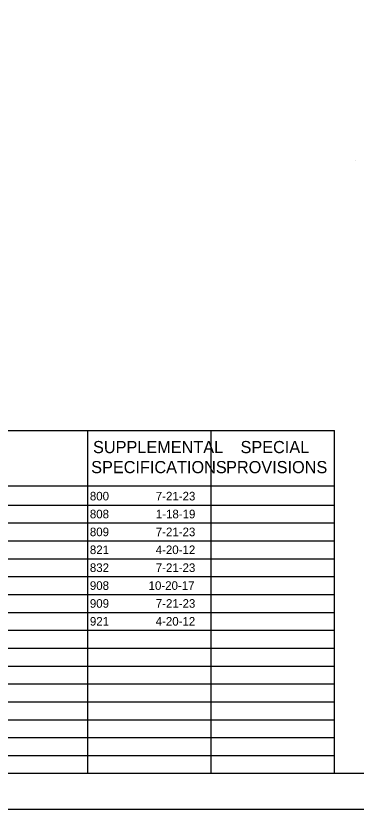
# Model space of a CAD drawing. Extents: x 0 to 34, y 0 to 22.
# Drawn here: x 20.25 to 25, y 0 to 11.09 of the extents above; entities that cross this region are included whole.
import ezdxf

# ---------------------------------------------------------------- set-up
doc = ezdxf.new("R2010")
doc.units = 0
for name, color, linetype in [('SH_Border', 7, 'Continuous'), ('SH_Cut_Line', 7, 'Continuous'), ('SH_Data', 7, 'Continuous'), ('SH_Text', 7, 'Continuous')]:
    doc.layers.add(name, color=color, linetype=linetype)

msp = doc.modelspace()

# ---------------------------------------------------------------- linework, layer by layer
at = {"layer": 'SH_Border'}
msp.add_lwpolyline([(1.5, 21.5), (33.5, 21.5), (33.5, 0.5), (1.5, 0.5)], close=True, dxfattribs=at)
at = {"layer": 'SH_Cut_Line'}
msp.add_lwpolyline([(0, 0), (34, 0), (34, 22), (0, 22)], close=True, dxfattribs=at)
at = {"layer": 'SH_Data'}
for p, q in [((25, 9.06), (25, 9.06)), ((11.25, 5.292), (24.7, 5.292)), ((21.25, 0.5), (21.25, 5.292)), ((22.975, 0.5), (22.975, 5.292)), ((24.7, 0.5), (24.7, 5.292)), ((11.25, 4.521), (24.7, 4.521)), ((11.25, 4.25), (24.7, 4.25)), ((11.25, 4), (24.7, 4)), ((11.25, 3.75), (24.7, 3.75)), ((11.25, 3.5), (24.7, 3.5)), ((11.25, 3.25), (24.7, 3.25)), ((11.25, 3), (24.7, 3)), ((11.25, 2.75), (24.7, 2.75)), ((11.25, 2.5), (24.7, 2.5)), ((11.25, 2.25), (24.7, 2.25)), ((11.25, 2), (24.7, 2)), ((11.25, 1.75), (24.7, 1.75)), ((11.25, 1.5), (24.7, 1.5)), ((11.25, 1.25), (24.7, 1.25)), ((11.25, 1), (24.7, 1)), ((11.25, 0.75), (24.7, 0.75))]:
    msp.add_line(p, q, dxfattribs=at)

# ---------------------------------------------------------------- texts
at = {"layer": 'SH_Text'}
for s, height, p in [('SUPPLEMENTAL', 0.17, (21.324, 4.976)), ('SPECIAL', 0.17, (23.386, 4.976)), ('SPECIFICATIONS', 0.17, (21.298, 4.696)), ('PROVISIONS', 0.17, (23.184, 4.696)), ('800', 0.12, (21.28, 4.315)), ('7-21-23', 0.12, (22.201, 4.315)), ('808', 0.12, (21.28, 4.065)), ('1-18-19', 0.12, (22.202, 4.065)), ('809', 0.12, (21.28, 3.815)), ('7-21-23', 0.12, (22.201, 3.815)), ('821', 0.12, (21.28, 3.565)), ('4-20-12', 0.12, (22.2, 3.565)), ('832', 0.12, (21.28, 3.315)), ('7-21-23', 0.12, (22.201, 3.315)), ('908', 0.12, (21.28, 3.065)), ('10-20-17', 0.12, (22.101, 3.065)), ('909', 0.12, (21.28, 2.815)), ('7-21-23', 0.12, (22.201, 2.815)), ('921', 0.12, (21.28, 2.565)), ('4-20-12', 0.12, (22.2, 2.565))]:
    msp.add_text(s, height=height, dxfattribs=at).set_placement(p)

doc.saveas('drawing.dxf')
